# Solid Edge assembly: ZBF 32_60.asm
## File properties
Title: Zylinder
Author: bmolnar
Template: iso metric assembly.asm
Last saved by: bmolnar
Revision: 20
Application: Solid Edge
Username: bmolnar
Dokumentum tartalom típus: 1
Document Number: ZBF 32/60
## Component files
Profilrohr.par
Kolbenstange.par
Kit.par
Mutter.par
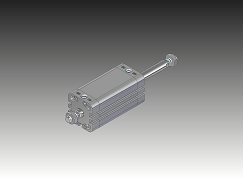
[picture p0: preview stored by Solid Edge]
